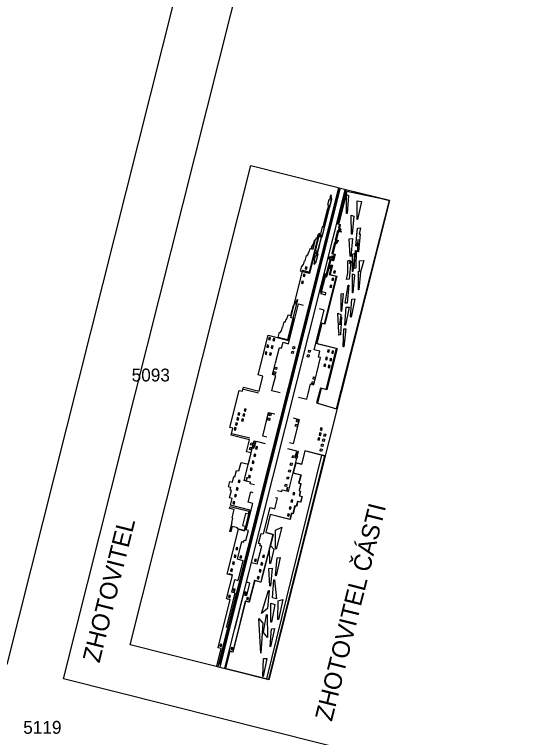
# Model space of a CAD drawing. Extents: x -740053 to -737517, y -1033516 to -1032488.
# Drawn here: x -738944.49 to -738922.67, y -1033022.69 to -1032991.77 of the extents above; entities that cross this region are included whole.
import ezdxf

# ---------------------------------------------------------------- set-up
doc = ezdxf.new("R2010")
doc.units = 0
doc.layers.add('bod-cislo', color=7, linetype='Continuous')
doc.layers.add('promika-rozp', color=7, linetype='Continuous')

# ---------------------------------------------------------------- blocks, each defined once
blk = doc.blocks.new('onegast')
for p, q in [((22.998, 7.759), (22.998, 9.646)), ((27.598, 8.019), (27.598, 9.571)), ((6.825, 5.723), (6.825, 6.082)), ((9.252, 6.105), (9.252, 6.463)), ((9.309, 6.102), (9.309, 6.46)), ((0.046, 5.264), (49.513, 5.263)), ((0.046, 5.075), (49.427, 5.075)), ((0.278, 5.186), (49.435, 5.186)), ((0.046, 4.561), (49.435, 4.561))]:
    blk.add_line(p, q)
for points in [[(0, 14.352), (49.53, 14.352), (49.53, 0), (0, 0)], [(23.451, 9.351), (23.667, 9.351), (23.667, 9.502), (23.451, 9.502)], [(23.957, 9.351), (24.173, 9.351), (24.173, 9.502), (23.957, 9.502)], [(24.48, 9.351), (24.696, 9.351), (24.696, 9.502), (24.48, 9.502)], [(24.994, 9.351), (25.21, 9.351), (25.21, 9.502), (24.994, 9.502)], [(24.501, 8.843), (24.717, 8.843), (24.717, 8.994), (24.501, 8.994)], [(25.007, 8.843), (25.223, 8.843), (25.223, 8.994), (25.007, 8.994)], [(25.53, 8.843), (25.746, 8.843), (25.746, 8.994), (25.53, 8.994)], [(21.914, 7.53), (22.13, 7.53), (22.13, 7.378), (21.914, 7.378)], [(22.377, 7.53), (22.593, 7.53), (22.593, 7.378), (22.377, 7.378)], [(19.161, 6.799), (19.377, 6.799), (19.377, 6.95), (19.161, 6.95)], [(29.857, 7.022), (30.073, 7.022), (30.073, 6.871), (29.857, 6.871)], [(30.32, 7.022), (30.536, 7.022), (30.536, 6.871), (30.32, 6.871)], [(25.216, 6.462), (25.432, 6.462), (25.432, 6.311), (25.216, 6.311)], [(25.679, 6.462), (25.895, 6.462), (25.895, 6.311), (25.679, 6.311)], [(32.298, 5.793), (32.514, 5.793), (32.514, 5.642), (32.298, 5.642)], [(32.761, 5.793), (32.977, 5.793), (32.977, 5.642), (32.761, 5.642)], [(25.286, 3.656), (25.502, 3.656), (25.502, 3.505), (25.286, 3.505)], [(25.749, 3.656), (25.965, 3.656), (25.965, 3.505), (25.749, 3.505)], [(32.333, 4.18), (32.549, 4.18), (32.549, 4.029), (32.333, 4.029)], [(32.796, 4.18), (33.012, 4.18), (33.012, 4.029), (32.796, 4.029)], [(12.874, 2.574), (14.701, 3.028), (15.132, 2.483), (12.879, 2.512)], [(19.195, 3.182), (19.411, 3.182), (19.411, 3.031), (19.195, 3.031)], [(29.843, 3.074), (30.059, 3.074), (30.059, 2.923), (29.843, 2.923)], [(30.306, 3.074), (30.522, 3.074), (30.522, 2.923), (30.306, 2.923)], [(3.464, 1.792), (5.689, 2.483), (5.353, 1.985), (2.388, 1.451)], [(6.257, 2.359), (8.663, 2.239), (8.678, 2.175), (6.892, 1.886)], [(9.139, 2.21), (10.813, 2.729), (10.929, 2.436), (9.143, 2.148)], [(10.285, 1.911), (12.061, 2.202), (12.15, 1.899), (10.289, 1.849)], [(4.449, 1.687), (6.263, 1.842), (6.277, 1.778), (4.06, 1.174)], [(5.644, 1.239), (7.471, 1.693), (7.457, 1.283), (5.649, 1.176)], [(8.049, 1.674), (9.825, 1.965), (9.84, 1.9), (8.039, 1.247)], [(0.161, 0.692), (1.912, 1.059), (2.012, 0.718), (0.165, 0.63)], [(3.24, 0.71), (5.016, 1), (5.119, 0.715), (3.244, 0.648)], [(6.077, 0.602), (7.903, 1.057), (8.126, 0.622), (6.081, 0.54)], [(24.501, 0.974), (24.717, 0.974), (24.717, 1.125), (24.501, 1.125)], [(25.007, 0.974), (25.223, 0.974), (25.223, 1.125), (25.007, 1.125)], [(25.53, 0.974), (25.746, 0.974), (25.746, 1.125), (25.53, 1.125)], [(23.485, 0.631), (23.701, 0.631), (23.701, 0.48), (23.485, 0.48)], [(23.99, 0.631), (24.206, 0.631), (24.206, 0.48), (23.99, 0.48)], [(24.513, 0.631), (24.729, 0.631), (24.729, 0.48), (24.513, 0.48)], [(25.028, 0.631), (25.244, 0.631), (25.244, 0.48), (25.028, 0.48)]]:
    blk.add_lwpolyline(points, close=True)
for points in [[(0.046, 5.405), (1.862, 5.405), (1.862, 5.731), (6.84, 5.731), (6.84, 6.109), (9.238, 6.109), (9.238, 6.643), (13.878, 6.643), (13.878, 6.005), (16.015, 6.005), (16.015, 8.023), (16.706, 8.023), (16.706, 8.284), (17.475, 8.284), (17.475, 8.401), (17.749, 8.401), (17.749, 8.662), (18.296, 8.662), (18.296, 8.388), (18.879, 8.388), (18.879, 8.272), (19.556, 8.272), (19.556, 8.037), (20.443, 8.037), (20.443, 7.282), (21.616, 7.282), (21.616, 7.764), (22.841, 7.764), (22.841, 9.665), (23.57, 9.665), (23.57, 9.994), (27.389, 9.994), (27.389, 9.629), (27.806, 9.629), (27.806, 8.014), (29.37, 8.014), (29.37, 8.522), (33.462, 8.522), (33.462, 6.412), (35.707, 6.412), (35.707, 6.737), (40.62, 6.737), (40.62, 6.034), (44.351, 6.034), (44.351, 5.656), (48.313, 5.656)], [(14.328, 6.074), (13.905, 6.074), (13.905, 6.765), (14, 6.765), (14, 7.326), (13.453, 7.326), (13.453, 7.425), (14.378, 7.425), (14.378, 7.475), (14.825, 7.475), (14.825, 7.544), (15.233, 7.544), (15.273, 7.544), (15.68, 7.544), (15.68, 8.021), (15.879, 8.021), (15.879, 6.074), (15.571, 6.074), (15.571, 6.362), (14.328, 6.362), (14.328, 6.074)], [(31.563, 8.207), (31.779, 8.207), (31.779, 8.358), (31.563, 8.358), (31.563, 8.207)], [(32.276, 8.207), (32.493, 8.207), (32.493, 8.358), (32.276, 8.358), (32.276, 8.207)], [(33.049, 8.207), (33.265, 8.207), (33.265, 8.358), (33.049, 8.358), (33.049, 8.207)], [(16.228, 7.685), (16.444, 7.685), (16.444, 7.836), (16.228, 7.836), (16.228, 7.685)], [(16.952, 7.685), (17.168, 7.685), (17.168, 7.836), (16.952, 7.836), (16.952, 7.685)], [(17.666, 7.685), (17.882, 7.685), (17.882, 7.836), (17.666, 7.836), (17.666, 7.685)], [(18.439, 7.685), (18.655, 7.685), (18.655, 7.836), (18.439, 7.836), (18.439, 7.685)], [(18.576, 6.169), (18.576, 6.617), (18.746, 6.617), (18.746, 7.081), (19.149, 7.081), (19.149, 7.081), (18.746, 7.081), (18.746, 7.282), (22.862, 7.282), (22.862, 7.282), (22.862, 7.183), (22.396, 7.183), (22.396, 7.088), (22.871, 7.088), (22.871, 6.157)], [(22.141, 7.131), (22.357, 7.131), (22.357, 7.282), (22.141, 7.282), (22.141, 7.131)], [(31.581, 7.761), (31.797, 7.761), (31.797, 7.913), (31.581, 7.913), (31.581, 7.761)], [(32.295, 7.761), (32.511, 7.761), (32.511, 7.913), (32.295, 7.913), (32.295, 7.761)], [(33.067, 7.761), (33.284, 7.761), (33.284, 7.913), (33.067, 7.913), (33.067, 7.761)], [(37.637, 6.532), (33.482, 6.532), (33.482, 7.473), (34.037, 7.473), (34.037, 7.386), (34.193, 7.386), (34.193, 7.317), (34.616, 7.317), (34.616, 7.275), (35.159, 7.275), (35.159, 7.197), (35.257, 7.197), (35.257, 7.144), (35.467, 7.144), (35.467, 7.095), (35.652, 7.095), (35.652, 7.062), (35.94, 7.062), (35.94, 6.779), (36.976, 6.779), (36.976, 6.725), (37.165, 6.725), (37.165, 6.639), (37.502, 6.639), (37.502, 6.565), (37.637, 6.565), (37.637, 6.532)], [(19.919, 6.799), (20.135, 6.799), (20.135, 6.95), (19.919, 6.95), (19.919, 6.799)], [(20.644, 6.799), (20.86, 6.799), (20.86, 6.95), (20.644, 6.95), (20.644, 6.799)], [(21.358, 6.799), (21.574, 6.799), (21.574, 6.95), (21.358, 6.95), (21.358, 6.799)], [(22.13, 6.799), (22.346, 6.799), (22.346, 6.95), (22.13, 6.95), (22.13, 6.799)], [(23.534, 6.16), (23.534, 6.579), (25.98, 6.579), (25.98, 5.951)], [(28.148, 5.929), (28.148, 6.792), (28.724, 6.792), (28.724, 6.792), (29.741, 6.792), (29.741, 7.118), (30.144, 7.118), (30.144, 7.118), (30.97, 7.118), (30.97, 7.118), (32.543, 7.118), (32.543, 6.888), (33.138, 6.888), (33.138, 6.313), (37.246, 6.313), (37.246, 5.833)], [(39.341, 6.398), (39.557, 6.398), (39.557, 6.549), (39.341, 6.549), (39.341, 6.398)], [(40.055, 6.398), (40.271, 6.398), (40.271, 6.549), (40.055, 6.549), (40.055, 6.398)], [(40.466, 6.007), (40.466, 6.948), (41.021, 6.948), (41.021, 6.861), (41.177, 6.861), (41.177, 6.792), (41.6, 6.792), (41.6, 6.75), (42.143, 6.75), (42.143, 6.672), (42.241, 6.672), (42.241, 6.619), (42.451, 6.619), (42.451, 6.57), (42.636, 6.57), (42.636, 6.537), (42.924, 6.537), (42.924, 6.254), (43.96, 6.254), (43.96, 6.2), (44.149, 6.2), (44.149, 6.114), (44.486, 6.114), (44.486, 6.04), (44.622, 6.04), (44.622, 6.007), (40.466, 6.007)], [(44.622, 6.007), (40.466, 6.007), (40.466, 6.948), (41.021, 6.948), (41.021, 6.861), (41.177, 6.861), (41.177, 6.792), (41.6, 6.792), (41.6, 6.75), (42.143, 6.75), (42.143, 6.672), (42.241, 6.672), (42.241, 6.619), (42.451, 6.619), (42.451, 6.57), (42.636, 6.57), (42.636, 6.537), (42.924, 6.537), (42.924, 6.254), (43.96, 6.254), (43.96, 6.2), (44.149, 6.2), (44.149, 6.114), (44.486, 6.114), (44.486, 6.04), (44.622, 6.04), (44.622, 6.007)], [(40.827, 6.398), (41.043, 6.398), (41.043, 6.549), (40.827, 6.549), (40.827, 6.398)], [(4.051, 5.42), (7.596, 5.42), (7.596, 5.765), (8.897, 5.765), (8.897, 5.42), (10.933, 5.42), (10.933, 6.01), (12.761, 6.01), (12.761, 5.826), (12.957, 5.826), (12.957, 5.643), (14, 5.643), (14, 5.888), (16.736, 5.888), (16.736, 6.366), (17.815, 6.366), (17.815, 6.145)], [(7.024, 5.813), (7.24, 5.813), (7.24, 5.964), (7.024, 5.964), (7.024, 5.813)], [(9.628, 6.243), (9.844, 6.243), (9.844, 6.394), (9.628, 6.394), (9.628, 6.243)], [(10.353, 6.243), (10.569, 6.243), (10.569, 6.394), (10.353, 6.394), (10.353, 6.243)], [(11.067, 6.243), (11.283, 6.243), (11.283, 6.394), (11.067, 6.394), (11.067, 6.243)], [(11.131, 5.681), (11.348, 5.681), (11.348, 5.832), (11.131, 5.832), (11.131, 5.681)], [(11.839, 6.243), (12.055, 6.243), (12.055, 6.394), (11.839, 6.394), (11.839, 6.243)], [(41.512, 5.831), (41.512, 5.707), (41.669, 5.707), (41.669, 5.636), (42.598, 5.636), (42.598, 5.694), (42.709, 5.694), (42.709, 5.727), (44.282, 5.727), (44.282, 5.811), (44.431, 5.811), (44.431, 5.844), (44.516, 5.844), (44.516, 5.681), (45.309, 5.681), (45.309, 5.74), (45.433, 5.74), (45.433, 5.779), (45.491, 5.779), (45.491, 5.805), (47.253, 5.805), (47.253, 5.707), (47.396, 5.707), (47.396, 5.649), (48.254, 5.649), (48.254, 5.727), (48.443, 5.727), (48.443, 5.785), (48.599, 5.785), (48.599, 5.87), (48.098, 5.87), (48.098, 5.922), (47.578, 5.922), (47.578, 5.831), (45.335, 5.831), (45.335, 5.902), (44.425, 5.902), (44.425, 5.772), (44.282, 5.772), (44.282, 5.746), (42.702, 5.746), (42.702, 5.811), (42.826, 5.811), (42.826, 5.967), (43.196, 5.967), (43.196, 6.019), (42.546, 6.019), (42.546, 5.863), (42.683, 5.863), (42.683, 5.798), (42.332, 5.798), (42.332, 5.87), (41.838, 5.87), (41.838, 5.824), (41.512, 5.831)], [(44.282, 5.727), (44.282, 5.746), (42.702, 5.746), (42.702, 5.811), (42.826, 5.811), (42.826, 5.967), (43.196, 5.967), (43.196, 6.019), (42.546, 6.019), (42.546, 5.863), (42.683, 5.863), (42.683, 5.798), (42.332, 5.798), (42.332, 5.87), (41.838, 5.87), (41.838, 5.824), (41.512, 5.831), (41.512, 5.707), (41.669, 5.707), (41.669, 5.636), (42.598, 5.636), (42.598, 5.694), (42.709, 5.694), (42.709, 5.727), (44.282, 5.727)], [(42.958, 6.466), (42.958, 6.276), (43.791, 6.276), (43.791, 6.348), (43.516, 6.348), (43.516, 6.365), (43.342, 6.365), (43.342, 6.413), (43.192, 6.413), (43.192, 6.466), (42.958, 6.466)], [(43.192, 6.466), (42.958, 6.466), (42.958, 6.276), (43.791, 6.276), (43.791, 6.348), (43.516, 6.348), (43.516, 6.365), (43.342, 6.365), (43.342, 6.413), (43.192, 6.413), (43.192, 6.466)], [(44.425, 5.772), (44.425, 5.811), (44.282, 5.811), (44.282, 5.772), (44.425, 5.772)], [(44.425, 5.902), (44.425, 5.811), (44.431, 5.811), (44.431, 5.844), (44.516, 5.844), (44.516, 5.681), (45.309, 5.681), (45.309, 5.74), (45.433, 5.74), (45.433, 5.779), (45.491, 5.779), (45.491, 5.805), (47.253, 5.805), (47.253, 5.707), (47.396, 5.707), (47.396, 5.649), (48.254, 5.649), (48.254, 5.727), (48.443, 5.727), (48.443, 5.785), (48.599, 5.785), (48.599, 5.87), (48.098, 5.87), (48.098, 5.922), (47.578, 5.922), (47.578, 5.831), (45.335, 5.831), (45.335, 5.902), (44.425, 5.902)], [(2.06, 5.439), (2.276, 5.439), (2.276, 5.591), (2.06, 5.591), (2.06, 5.439)], [(7.749, 5.505), (7.965, 5.505), (7.965, 5.656), (7.749, 5.656), (7.749, 5.505)], [(0.02, 0.014), (23.093, 0.002), (23.125, 2.114), (22.3, 2.114), (21.766, 2.106), (21.766, 2.114), (21.714, 2.114), (21.714, 2.69), (20.694, 2.699), (20.694, 2.513), (20.708, 1.897), (19.841, 1.924), (19.841, 1.714), (19.819, 1.714), (19.819, 1.69), (19.163, 1.69), (19.103, 1.687), (19.103, 1.544), (18.635, 1.544), (18.625, 1.386), (18.625, 1.266), (18.256, 1.266), (18.026, 1.258), (18.017, 1.57), (17.525, 1.57), (17.525, 1.716), (16.716, 1.716), (16.716, 1.896), (16.101, 1.86), (16.101, 1.902), (16.093, 1.902), (16.093, 2.719), (16.083, 3.915), (14.514, 3.915), (14.249, 3.911), (14.237, 3.714), (14.237, 3.187), (14.206, 3.187), (14.203, 3.146), (13.089, 3.156), (12.812, 2.735), (11.338, 2.693), (11.334, 2.755), (12.803, 3.159), (9.776, 3.187), (9.292, 3.187), (9.292, 3.191), (9.287, 3.191), (9.292, 3.593), (9.292, 3.82), (7.066, 3.831), (7.065, 3.849), (7.039, 3.849), (7.039, 4.196), (2.893, 4.204), (2.028, 4.198), (1.802, 4.187), (1.803, 4.196), (1.802, 4.196), (1.81, 4.518), (0.042, 4.506), (0.02, 0.014)], [(0.042, 4.506), (0.03, 0.238), (23.125, 0.347), (23.125, 2.125), (21.766, 2.106), (21.748, 2.69), (20.689, 2.699), (20.708, 1.897), (19.841, 1.924), (19.841, 1.714), (19.093, 1.687), (19.093, 1.559), (18.637, 1.568), (18.619, 1.277), (18.026, 1.258), (18.017, 1.605), (17.542, 1.596), (17.542, 1.769), (16.721, 1.751), (16.73, 1.897), (16.101, 1.86), (16.083, 3.939), (14.249, 3.911), (14.203, 3.146), (9.287, 3.191), (9.296, 3.82), (7.066, 3.831), (7.048, 4.196), (2.185, 4.205), (1.802, 4.187), (1.821, 4.518), (0.042, 4.506)], [(0.036, 4.579), (0.065, 0.028), (23.119, 0.038), (23.133, 2.114), (21.714, 2.114), (21.714, 2.699), (20.694, 2.699), (20.694, 1.928), (19.819, 1.928), (19.819, 1.69), (19.103, 1.69), (19.103, 1.544), (18.625, 1.544), (18.625, 1.266), (18.029, 1.266), (18.029, 1.57), (17.525, 1.57), (17.525, 1.716), (16.716, 1.716), (16.716, 1.902), (16.093, 1.902), (16.093, 3.915), (14.237, 3.915), (14.237, 3.187), (9.292, 3.187), (9.292, 3.849), (7.039, 3.849), (7.039, 4.233), (1.802, 4.196), (1.811, 4.57), (0.036, 4.579)], [(1.994, 4.298), (2.21, 4.298), (2.21, 4.449), (1.994, 4.449), (1.994, 4.298)], [(4.084, 4.561), (7.63, 4.561), (7.63, 4.216), (8.93, 4.216), (8.93, 4.561), (10.967, 4.561), (10.967, 3.971), (12.794, 3.971), (12.794, 4.155), (12.991, 4.155), (12.991, 4.339), (14.034, 4.339), (14.034, 4.094), (16.769, 4.094), (16.769, 3.616), (17.849, 3.616), (17.849, 3.836)], [(7.727, 4.32), (7.943, 4.32), (7.943, 4.471), (7.727, 4.471), (7.727, 4.32)], [(28.067, 2.05), (27.99, 0.054), (49.512, 0.016), (49.361, 4.382), (46.076, 4.382), (46.076, 4.478), (46.005, 4.478), (46.005, 4.215), (45.632, 4.215), (45.632, 4.138), (45.529, 4.138), (45.529, 4.054), (45.349, 4.054), (45.349, 3.945), (45.259, 3.945), (45.259, 4.099), (45.439, 4.054), (45.439, 4.129), (45.439, 4.133), (45.471, 4.133), (45.471, 4.178), (45.282, 4.178), (45.282, 4.224), (44.334, 4.224), (44.334, 4.182), (44.184, 4.182), (44.184, 4.122), (44.287, 4.122), (44.287, 4.084), (44.394, 4.084), (44.394, 4.026), (44.258, 4.026), (44.258, 4.073), (44.068, 4.073), (44.068, 4.127), (44.012, 4.127), (44.012, 4.173), (44.086, 4.173), (44.086, 4.227), (42.971, 4.227), (42.971, 3.984), (42.289, 3.984), (42.289, 4.035), (42.5, 4.035), (42.5, 4.084), (42.652, 4.084), (42.652, 4.131), (42.701, 4.131), (42.701, 4.178), (42.514, 4.178), (42.514, 4.235), (42.596, 4.235), (42.596, 4.367), (42.482, 4.367), (42.482, 4.433), (42.389, 4.433), (42.389, 4.269), (40.819, 4.269), (40.819, 4.456), (40.717, 4.456), (40.717, 4.402), (40.569, 4.402), (40.569, 4.429), (38.993, 4.429), (38.993, 4.376), (38.881, 4.376), (38.881, 4.427), (38.792, 4.427), (38.792, 3.942), (38.993, 3.942), (38.993, 4.374), (40.564, 4.374), (40.564, 4.225), (41.633, 4.225), (41.633, 4.187), (41.484, 4.187), (41.484, 4.078), (41.635, 4.078), (41.635, 4.029), (41.831, 4.029), (41.831, 3.98), (40.874, 3.98), (40.874, 3.262), (35.926, 3.262), (35.926, 3.569), (33.862, 3.569), (33.862, 1.483), (29.594, 1.483), (29.594, 2.051), (28.067, 2.05)], [(28.067, 2.141), (27.991, 0.053), (49.525, -0.002), (49.509, 4.521), (46.076, 4.473), (46.076, 4.57), (46.005, 4.57), (46.005, 4.306), (45.632, 4.306), (45.632, 4.229), (45.529, 4.229), (45.529, 4.146), (45.439, 4.146), (45.349, 4.146), (45.349, 4.036), (45.259, 4.036), (45.259, 4.191), (45.439, 4.146), (45.439, 4.22), (45.439, 4.224), (45.471, 4.224), (45.471, 4.269), (45.282, 4.269), (45.282, 4.316), (44.334, 4.316), (44.334, 4.273), (44.184, 4.273), (44.184, 4.213), (44.287, 4.213), (44.287, 4.176), (44.394, 4.176), (44.394, 4.118), (44.258, 4.118), (44.258, 4.164), (44.068, 4.164), (44.068, 4.218), (44.012, 4.218), (44.012, 4.265), (44.086, 4.265), (44.086, 4.318), (42.971, 4.318), (42.971, 4.076), (42.289, 4.076), (42.289, 4.126), (42.5, 4.126), (42.5, 4.175), (42.652, 4.175), (42.652, 4.222), (42.701, 4.222), (42.701, 4.269), (42.514, 4.269), (42.514, 4.327), (42.596, 4.327), (42.596, 4.458), (42.482, 4.458), (42.482, 4.525), (42.389, 4.525), (42.389, 4.36), (40.819, 4.36), (40.819, 4.547), (40.717, 4.547), (40.717, 4.494), (40.569, 4.494), (40.569, 4.52), (38.993, 4.52), (38.993, 4.465), (40.564, 4.465), (40.564, 4.316), (41.633, 4.316), (41.633, 4.278), (41.484, 4.278), (41.484, 4.169), (41.635, 4.169), (41.635, 4.12), (41.831, 4.12), (41.831, 4.071), (40.874, 4.071), (40.874, 3.353), (35.926, 3.353), (35.926, 3.66), (33.862, 3.66), (33.862, 1.575), (29.594, 1.575), (29.594, 2.142), (28.067, 2.141)], [(7.243, 3.99), (7.46, 3.99), (7.46, 4.142), (7.243, 4.142), (7.243, 3.99)], [(11.175, 4.166), (11.391, 4.166), (11.391, 4.317), (11.175, 4.317), (11.175, 4.166)], [(18.61, 3.813), (18.61, 3.364), (18.78, 3.364), (18.78, 2.9), (19.182, 2.9), (19.182, 2.9), (18.78, 2.9), (18.78, 2.699), (22.895, 2.699), (22.895, 2.699), (22.895, 2.799), (22.429, 2.799), (22.429, 2.894), (22.904, 2.894), (22.904, 3.824)], [(23.568, 3.821), (23.568, 3.403), (26.014, 3.403), (26.014, 4.03)], [(28.182, 4.052), (28.182, 3.189), (28.757, 3.189), (28.757, 3.189), (29.775, 3.189), (29.775, 2.863), (30.178, 2.863), (30.178, 2.863), (31.003, 2.863), (31.003, 2.863), (32.577, 2.863), (32.577, 3.093), (33.172, 3.093), (33.172, 3.669), (37.279, 3.669), (37.279, 4.148)], [(39.65, 3.525), (39.866, 3.525), (39.866, 3.677), (39.65, 3.677), (39.65, 3.525)], [(40.364, 3.525), (40.58, 3.525), (40.58, 3.677), (40.364, 3.677), (40.364, 3.525)], [(41.136, 3.525), (41.352, 3.525), (41.352, 3.677), (41.136, 3.677), (41.136, 3.525)], [(49.007, 4.105), (47.221, 3.817), (47.216, 3.879), (49.043, 4.334), (49.007, 4.105)], [(9.536, 3.464), (9.752, 3.464), (9.752, 3.615), (9.536, 3.615), (9.536, 3.464)], [(10.26, 3.464), (10.476, 3.464), (10.476, 3.615), (10.26, 3.615), (10.26, 3.464)], [(10.974, 3.464), (11.19, 3.464), (11.19, 3.615), (10.974, 3.615), (10.974, 3.464)], [(11.746, 3.464), (11.963, 3.464), (11.963, 3.615), (11.746, 3.615), (11.746, 3.464)], [(15.132, 2.483), (12.879, 2.512), (12.874, 2.574), (14.701, 3.028), (15.132, 2.483)], [(19.195, 3.031), (19.195, 3.182), (19.411, 3.182), (19.411, 3.031), (19.195, 3.031)], [(20.169, 3.031), (19.953, 3.031), (19.953, 3.182), (20.169, 3.182), (20.169, 3.031)], [(20.893, 3.031), (20.677, 3.031), (20.677, 3.182), (20.893, 3.182), (20.893, 3.031)], [(21.607, 3.031), (21.391, 3.031), (21.391, 3.182), (21.607, 3.182), (21.607, 3.031)], [(22.38, 3.031), (22.164, 3.031), (22.164, 3.182), (22.38, 3.182), (22.38, 3.031)], [(44.937, 2.689), (43.151, 2.401), (43.147, 2.463), (44.821, 2.982), (44.937, 2.689)], [(47.132, 3.109), (45.346, 2.82), (45.342, 2.882), (47.162, 3.382), (47.132, 3.109)], [(48.753, 2.715), (46.887, 2.639), (46.882, 2.701), (48.709, 3.155), (48.753, 2.715)], [(2.388, 1.451), (3.464, 1.792), (5.689, 2.483), (5.353, 1.985), (2.388, 1.451)], [(6.892, 1.886), (6.257, 2.359), (8.663, 2.239), (8.678, 2.175), (6.892, 1.886)], [(9.143, 2.148), (9.139, 2.21), (10.813, 2.729), (10.929, 2.436), (9.143, 2.148)], [(10.289, 1.849), (10.285, 1.911), (12.061, 2.202), (12.15, 1.899), (10.289, 1.849)], [(16.383, 2.065), (16.599, 2.065), (16.599, 2.216), (16.383, 2.216), (16.383, 2.065)], [(17.107, 2.065), (17.324, 2.065), (17.324, 2.216), (17.107, 2.216), (17.107, 2.065)], [(17.821, 2.065), (18.037, 2.065), (18.037, 2.216), (17.821, 2.216), (17.821, 2.065)], [(18.594, 2.065), (18.81, 2.065), (18.81, 2.216), (18.594, 2.216), (18.594, 2.065)], [(22.39, 2.699), (22.174, 2.699), (22.174, 2.85), (22.39, 2.85), (22.39, 2.699)], [(31.804, 2.197), (32.02, 2.197), (32.02, 2.348), (31.804, 2.348), (31.804, 2.197)], [(32.518, 2.197), (32.734, 2.197), (32.734, 2.348), (32.518, 2.348), (32.518, 2.197)], [(33.29, 2.197), (33.506, 2.197), (33.506, 2.348), (33.29, 2.348), (33.29, 2.197)], [(37.045, 1.826), (35.275, 1.483), (35.212, 1.656), (35.458, 1.687), (35.456, 1.725), (37.304, 2.273), (37.246, 1.951), (36.232, 1.787), (37.03, 1.89), (37.045, 1.826)], [(39.361, 2.237), (37.575, 1.949), (37.57, 2.011), (39.263, 2.411), (39.361, 2.237)], [(42.686, 2.302), (40.9, 2.014), (40.791, 2.246), (41.431, 2.287), (42.647, 2.574), (42.745, 2.401), (42.436, 2.351), (42.671, 2.366), (42.686, 2.302)], [(43.522, 2.115), (41.736, 1.826), (41.732, 1.888), (43.425, 2.288), (43.522, 2.115)], [(45.555, 2.06), (43.769, 1.772), (43.765, 1.834), (44.98, 2.121), (44.297, 2.102), (44.293, 2.164), (46.069, 2.455), (46.158, 2.152), (45.513, 2.135), (45.555, 2.06)], [(4.06, 1.174), (4.449, 1.687), (6.263, 1.842), (6.277, 1.778), (4.06, 1.174)], [(5.649, 1.176), (5.644, 1.239), (7.471, 1.693), (7.457, 1.283), (5.649, 1.176)], [(8.039, 1.247), (8.049, 1.674), (9.825, 1.965), (9.84, 1.9), (8.039, 1.247)], [(31.804, 1.752), (32.02, 1.752), (32.02, 1.903), (31.804, 1.903), (31.804, 1.752)], [(32.518, 1.752), (32.734, 1.752), (32.734, 1.903), (32.518, 1.903), (32.518, 1.752)], [(33.29, 1.752), (33.506, 1.752), (33.506, 1.903), (33.29, 1.903), (33.29, 1.752)], [(38.172, 1.324), (36.328, 1.254), (36.324, 1.316), (38.1, 1.607), (38.172, 1.324)], [(40.285, 1.905), (38.499, 1.617), (38.457, 1.814), (40.271, 1.97), (40.285, 1.905)], [(41.443, 1.592), (39.657, 1.304), (39.653, 1.366), (41.479, 1.82), (41.443, 1.592)], [(43.848, 2.028), (42.108, 1.637), (42.057, 1.801), (43.833, 2.092), (43.848, 2.028)], [(0.165, 0.63), (0.161, 0.692), (1.912, 1.059), (2.012, 0.718), (0.165, 0.63)], [(3.244, 0.648), (3.24, 0.71), (5.016, 1), (5.119, 0.715), (3.244, 0.648)], [(6.081, 0.54), (6.077, 0.602), (7.903, 1.057), (8.126, 0.622), (6.081, 0.54)], [(35.996, 1.11), (34.173, 0.883), (34.169, 0.945), (35.92, 1.312), (35.996, 1.11)], [(39.127, 0.968), (37.252, 0.901), (37.248, 0.963), (39.024, 1.253), (39.127, 0.968)], [(41.875, 1.082), (40.089, 0.793), (40.085, 0.855), (41.911, 1.31), (41.894, 1.2), (42.92, 1.442), (43.064, 1.042), (41.875, 1.085), (41.875, 1.082)]]:
    blk.add_lwpolyline(points)

msp = doc.modelspace()

# ---------------------------------------------------------------- linework, layer by layer
at = {"layer": 'promika-rozp'}
for points in [[(-738932.779, -1032929.787), (-738922.839, -1032932.289), (-738944.81, -1033019.566), (-738954.75, -1033017.063)], [(-738922.506, -1033025.181), (-738942.386, -1033020.176), (-738920.415, -1032932.899), (-738900.535, -1032937.904)]]:
    msp.add_lwpolyline(points, dxfattribs=at)

# ---------------------------------------------------------------- block references
at = {"xscale": 0.4267458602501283, "yscale": 0.4267458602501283, "rotation": 75.86979040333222}
msp.add_blockref('onegast', (-738933.603, -1033020.221), dxfattribs=at)

# ---------------------------------------------------------------- texts
at = {"layer": 'bod-cislo'}
for s, p in [('5093', (-738939.478, -1033007.463)), ('5119', (-738944.115, -1033022.533))]:
    msp.add_text(s, height=0.55, dxfattribs=at).set_placement(p)
at = {"layer": 'promika-rozp'}
for s, p in [('ZHOTOVITEL ČÁSTI', (-738930.917, -1033022.034)), ('ZHOTOVITEL', (-738940.857, -1033019.531))]:
    msp.add_text(s, height=0.75, rotation=75.8698, dxfattribs=at).set_placement(p)

doc.saveas('drawing.dxf')
